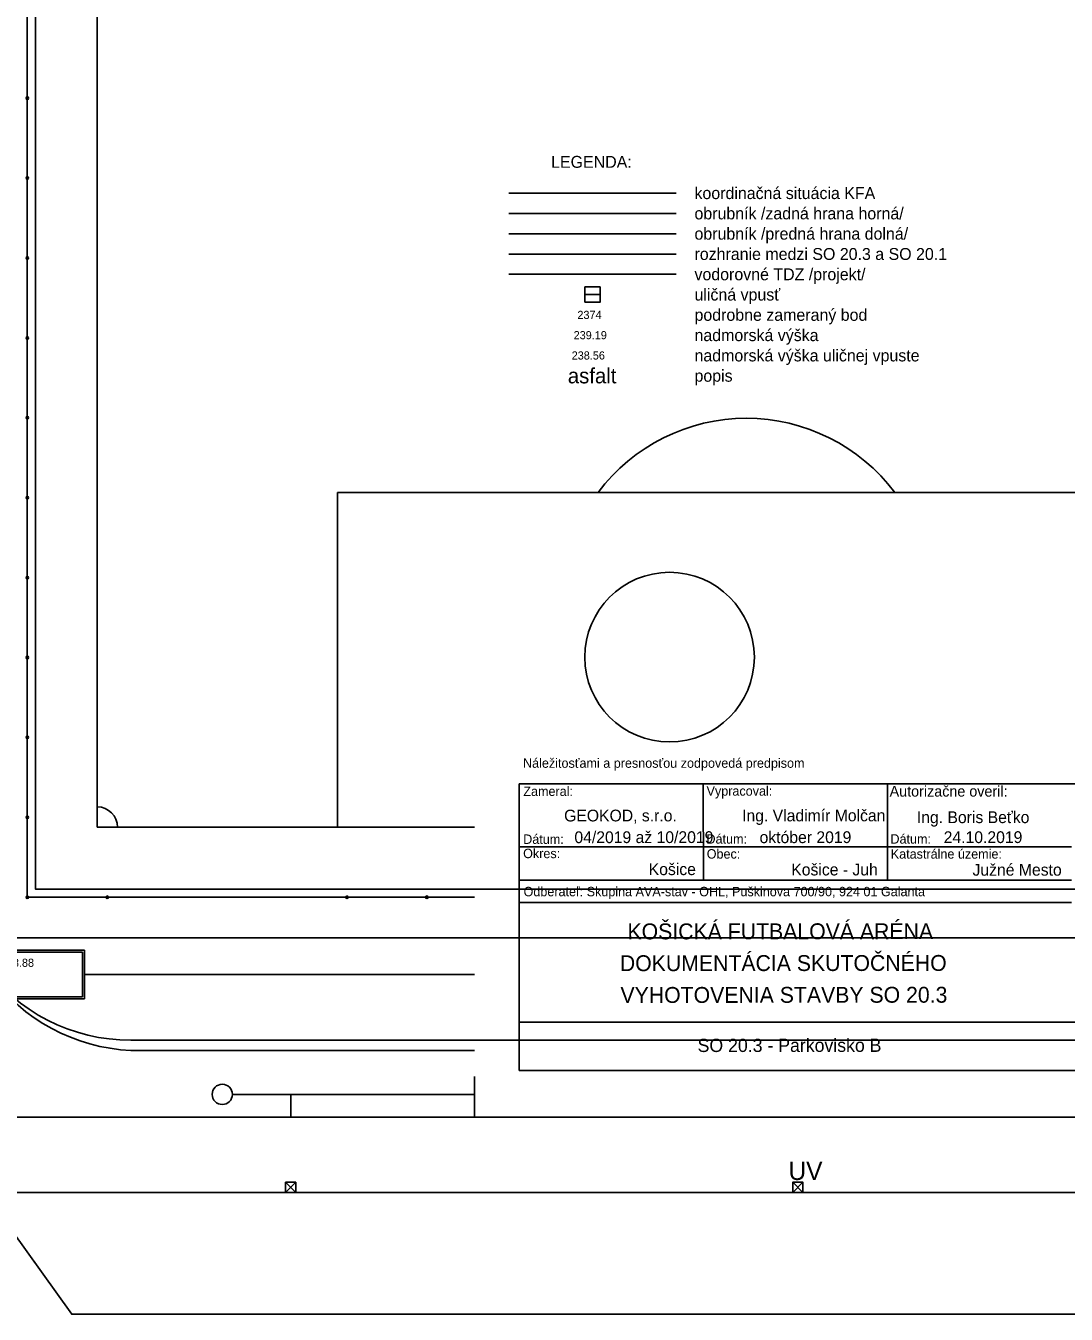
# Model space of a CAD drawing. Extents: x -264222 to -263676, y -1242344 to -1242060.
# Drawn here: x -264118.1 to -264066.8, y -1242315 to -1242251.5 of the extents above; entities that cross this region are included whole.
import ezdxf

# ---------------------------------------------------------------- set-up
doc = ezdxf.new("R2010")
doc.units = 0
for name, color, linetype in [('BODY_VYSKA', 7, 'Continuous'), ('KOORDINACNA_SITUACIA_DSP', 7, 'Continuous'), ('LEGENDA', 7, 'Continuous'), ('PROJEKT_DRS_OBRUBNIKY_KOMUNIKACIE', 7, 'Continuous'), ('PROJEKT_DRS_TDZ_VODOROVNE', 7, 'Continuous'), ('PROJEKT_DRS_UV_STAVBY', 7, 'Continuous'), ('RAM_NA_TLAC_8xA4_1-200', 7, 'Continuous'), ('ROZPISKA', 7, 'Continuous')]:
    doc.layers.add(name, color=color, linetype=linetype)

msp = doc.modelspace()

# ---------------------------------------------------------------- linework, layer by layer
at = {"layer": 'KOORDINACNA_SITUACIA_DSP'}
for p, q in [((-264118.068, -1242187.532), (-264118.068, -1242294.432)), ((-264117.668, -1242294.032), (-264117.668, -1242187.932)), ((-264114.618, -1242190.982), (-264114.618, -1242290.982)), ((-264118.008, -1242255.057), (-264118.128, -1242255.057)), ((-264118.068, -1242255.117), (-264118.068, -1242254.997)), ((-264118.008, -1242258.995), (-264118.128, -1242258.995)), ((-264118.068, -1242259.055), (-264118.068, -1242258.935)), ((-264118.008, -1242262.932), (-264118.128, -1242262.932)), ((-264118.068, -1242262.992), (-264118.068, -1242262.872)), ((-264118.068, -1242266.93), (-264118.068, -1242266.81)), ((-264118.008, -1242266.87), (-264118.128, -1242266.87)), ((-264118.008, -1242270.807), (-264118.128, -1242270.807)), ((-264118.068, -1242270.867), (-264118.068, -1242270.747)), ((-264118.008, -1242274.745), (-264118.128, -1242274.745)), ((-264118.068, -1242274.805), (-264118.068, -1242274.685)), ((-264062.458, -1242274.482), (-264102.778, -1242274.482)), ((-264102.778, -1242274.482), (-264102.778, -1242290.982)), ((-264118.008, -1242278.682), (-264118.128, -1242278.682)), ((-264118.068, -1242278.742), (-264118.068, -1242278.622)), ((-264118.008, -1242282.62), (-264118.128, -1242282.62)), ((-264118.068, -1242282.68), (-264118.068, -1242282.56)), ((-264118.068, -1242286.617), (-264118.068, -1242286.497)), ((-264118.008, -1242286.557), (-264118.128, -1242286.557)), ((-264118.008, -1242290.495), (-264118.128, -1242290.495)), ((-264118.068, -1242290.555), (-264118.068, -1242290.435)), ((-264114.618, -1242290.982), (-264096.03, -1242290.982)), ((-264096.03, -1242294.032), (-264117.668, -1242294.032)), ((-264118.008, -1242294.432), (-264118.128, -1242294.432)), ((-264118.068, -1242294.492), (-264118.068, -1242294.372)), ((-264118.068, -1242294.432), (-264096.03, -1242294.432)), ((-264114.069, -1242294.432), (-264114.189, -1242294.432)), ((-264114.129, -1242294.492), (-264114.129, -1242294.372)), ((-264102.252, -1242294.432), (-264102.372, -1242294.432)), ((-264102.312, -1242294.492), (-264102.312, -1242294.372)), ((-264098.313, -1242294.432), (-264098.433, -1242294.432)), ((-264098.373, -1242294.492), (-264098.373, -1242294.372)), ((-264115.254, -1242297.036), (-264120.154, -1242297.036)), ((-264115.354, -1242297.136), (-264120.054, -1242297.136)), ((-264115.354, -1242299.336), (-264115.354, -1242297.136)), ((-264115.254, -1242299.436), (-264115.254, -1242297.036)), ((-264115.254, -1242298.236), (-264096.03, -1242298.236)), ((-264120.154, -1242299.436), (-264115.254, -1242299.436)), ((-264120.054, -1242299.336), (-264115.354, -1242299.336)), ((-264096.03, -1242301.482), (-264112.961, -1242301.482)), ((-264096.03, -1242304.147), (-264107.955, -1242304.147)), ((-264105.085, -1242305.266), (-264105.085, -1242304.147))]:
    msp.add_line(p, q, dxfattribs=at)
msp.add_lwpolyline([(-264096.03, -1242296.432), (-264120.018, -1242296.432), (-264120.282, -1242296.432)], dxfattribs=at)
for centre, radius in [((-264118.068, -1242255.057), 0.06), ((-264118.068, -1242258.995), 0.06), ((-264118.068, -1242262.932), 0.06), ((-264118.068, -1242266.87), 0.06), ((-264118.068, -1242270.807), 0.06), ((-264118.068, -1242274.745), 0.06), ((-264118.068, -1242278.682), 0.06), ((-264118.068, -1242282.62), 0.06), ((-264118.068, -1242286.557), 0.06), ((-264118.068, -1242290.495), 0.06), ((-264118.068, -1242294.432), 0.06), ((-264114.129, -1242294.432), 0.06), ((-264102.312, -1242294.432), 0.06), ((-264098.373, -1242294.432), 0.06), ((-264108.455, -1242304.147), 0.5)]:
    msp.add_circle(centre, radius, dxfattribs=at)
for centre, radius, start, end in [((-264082.618, -1242279.982), 9.15, 36.94821, 143.05179), ((-264114.618, -1242290.982), 1, 0, 90), ((-264112.961, -1242292.482), 9, 215.72401, 270)]:
    msp.add_arc(centre, radius, start, end, dxfattribs=at)
at = {"layer": 'LEGENDA'}
for p, q in [((-264094.33, -1242259.736), (-264086.079, -1242259.736)), ((-264094.33, -1242260.736), (-264086.079, -1242260.736)), ((-264094.33, -1242261.736), (-264086.079, -1242261.736)), ((-264094.33, -1242262.736), (-264086.079, -1242262.736)), ((-264094.33, -1242263.736), (-264086.079, -1242263.736))]:
    msp.add_line(p, q, dxfattribs=at)
for points in [[(-264090.579, -1242264.361), (-264089.829, -1242264.361), (-264089.829, -1242265.111), (-264090.579, -1242265.111)], [(-264090.579, -1242265.111), (-264090.579, -1242264.361)], [(-264090.579, -1242264.736), (-264089.829, -1242264.736)]]:
    msp.add_lwpolyline(points, dxfattribs=at)
at = {"layer": 'PROJEKT_DRS_OBRUBNIKY_KOMUNIKACIE'}
for p, q in [((-264204.694, -1242191.482), (-264115.871, -1242314.982)), ((-263971.068, -1242301.482), (-264112.961, -1242301.482)), ((-264050.531, -1242308.982), (-264119.571, -1242308.982)), ((-264115.886, -1242314.982), (-264044.531, -1242314.982))]:
    msp.add_line(p, q, dxfattribs=at)
for points in [[(-264117.668, -1242187.932), (-264047.568, -1242187.932), (-264047.568, -1242294.032), (-264117.668, -1242294.032), (-264117.668, -1242187.932)], [(-263965.143, -1242296.432), (-264120.018, -1242296.432), (-264120.282, -1242296.432)]]:
    msp.add_lwpolyline(points, dxfattribs=at)
msp.add_arc((-264112.961, -1242292.482), 9, 215.72401, 270, dxfattribs=at)
at = {"layer": 'PROJEKT_DRS_TDZ_VODOROVNE'}
msp.add_line((-264112.961, -1242301.982), (-264096.03, -1242301.982), dxfattribs=at)
msp.add_arc((-264112.56, -1242292.924), 9.068, 215.87399, 267.4682, dxfattribs=at)
at = {"layer": 'PROJEKT_DRS_UV_STAVBY'}
for points in [[(-264105.335, -1242308.982), (-264105.335, -1242308.482), (-264104.835, -1242308.482), (-264104.835, -1242308.982), (-264105.335, -1242308.982), (-264104.835, -1242308.482), (-264105.335, -1242308.482), (-264104.835, -1242308.982)], [(-264080.335, -1242308.982), (-264080.335, -1242308.482), (-264079.835, -1242308.482), (-264079.835, -1242308.982), (-264080.335, -1242308.982), (-264079.835, -1242308.482), (-264080.335, -1242308.482), (-264079.835, -1242308.982)]]:
    msp.add_lwpolyline(points, dxfattribs=at)
at = {"layer": 'RAM_NA_TLAC_8xA4_1-200'}
msp.add_line((-264096.03, -1242305.266), (-264096.03, -1242303.266), dxfattribs=at)
msp.add_lwpolyline([(-264222.03, -1242186.466), (-264054.03, -1242186.466), (-264054.03, -1242305.266), (-264222.03, -1242305.266)], close=True, dxfattribs=at)
at = {"layer": 'ROZPISKA'}
for p, q in [((-264093.815, -1242288.848), (-264093.816, -1242302.965)), ((-264093.815, -1242288.848), (-264056.508, -1242288.848)), ((-264084.742, -1242288.847), (-264084.739, -1242293.589)), ((-264075.667, -1242288.85), (-264075.665, -1242293.587)), ((-264093.817, -1242291.946), (-264066.591, -1242291.946)), ((-264093.816, -1242293.587), (-264066.592, -1242293.587)), ((-264093.818, -1242294.699), (-264066.588, -1242294.696)), ((-264093.816, -1242300.585), (-264056.507, -1242300.584)), ((-264093.816, -1242302.965), (-264056.508, -1242302.965))]:
    msp.add_line(p, q, dxfattribs=at)
msp.add_circle((-264086.404, -1242282.601), 4.18, dxfattribs=at)

# ---------------------------------------------------------------- texts
at = {"layer": 'BODY_VYSKA'}
msp.add_text('238.88', height=0.4, dxfattribs=at).set_placement((-264119.374, -1242297.862))
at = {"layer": 'LEGENDA'}
for s, height, p in [('LEGENDA:', 0.5878, (-264092.245, -1242258.489)), ('koordinačná situácia KFA', 0.58781, (-264085.177, -1242260.029)), ('obrubník /zadná hrana horná/', 0.58781, (-264085.177, -1242261.029)), ('obrubník /predná hrana dolná/', 0.58781, (-264085.177, -1242262.029)), ('rozhranie medzi SO 20.3 a SO 20.1', 0.58781, (-264085.177, -1242263.029)), ('vodorovné TDZ /projekt/', 0.58781, (-264085.177, -1242264.029)), ('uličná vpusť', 0.58781, (-264085.177, -1242265.029)), ('2374', 0.4, (-264090.949, -1242265.936)), ('podrobne zameraný bod', 0.58781, (-264085.177, -1242266.029)), ('239.19', 0.4, (-264091.134, -1242266.936)), ('nadmorská výška', 0.58781, (-264085.177, -1242267.029)), ('nadmorská výška uličnej vpuste', 0.58781, (-264085.177, -1242268.029)), ('238.56', 0.4, (-264091.23, -1242267.936)), ('asfalt', 0.75, (-264091.422, -1242269.111)), ('popis', 0.5878, (-264085.177, -1242269.029))]:
    msp.add_text(s, height=height, dxfattribs=at).set_placement(p)
at = {"layer": 'PROJEKT_DRS_UV_STAVBY'}
msp.add_text('UV', height=0.9, rotation=359.8587, dxfattribs=at).set_placement((-264080.543, -1242308.366))
at = {"layer": 'ROZPISKA'}
for s, height, rotation, p in [('Náležitosťami a presnosťou zodpovedá predpisom', 0.46373, 0.00155, (-264093.629, -1242288.054)), ('Zameral:', 0.4637, 0.00155, (-264093.615, -1242289.442)), ('Vypracoval:', 0.46373, 0.00155, (-264084.582, -1242289.429)), ('Autorizačne overil:', 0.52854, 0.00155, (-264075.557, -1242289.474)), ('GEOKOD, s.r.o.', 0.57952, 0.04559, (-264091.603, -1242290.699)), ('Ing. Vladimír Molčan', 0.57964, 0.04559, (-264082.83, -1242290.697)), ('Ing. Boris Beťko', 0.57992, 0.04559, (-264074.215, -1242290.783)), ('Dátum:', 0.4637, 0.00155, (-264093.621, -1242291.804)), ('04/2019 až 10/2019', 0.57952, 0.04559, (-264091.097, -1242291.767)), ('Dátum:', 0.4637, 0.00155, (-264084.587, -1242291.791)), ('október 2019', 0.57952, 0.04559, (-264081.967, -1242291.767)), ('Dátum:', 0.4637, 0.00155, (-264075.517, -1242291.792)), ('24.10.2019', 0.5795, 0.04559, (-264072.891, -1242291.765)), ('Okres:', 0.4637, 0.00155, (-264093.624, -1242292.507)), ('Obec:', 0.4637, 0.00155, (-264084.574, -1242292.529)), ('Katastrálne územie:', 0.46373, 0.00155, (-264075.5, -1242292.531)), ('Košice', 0.5798, 0.04559, (-264087.433, -1242293.344)), ('Košice - Juh', 0.57992, 0.04559, (-264080.406, -1242293.361)), ('Južné Mesto', 0.57992, 0.04559, (-264071.47, -1242293.372)), ('Odberateľ: Skupina AVA-stav - OHL, Puškinova 700/90, 924 01 Galanta', 0.46361, 0.00155, (-264093.603, -1242294.386)), ('KOŠICKÁ FUTBALOVÁ ARÉNA', 0.78289, 0.04559, (-264088.482, -1242296.51)), ('DOKUMENTÁCIA SKUTOČNÉHO', 0.78289, 0.04559, (-264088.856, -1242298.076)), ('VYHOTOVENIA STAVBY SO 20.3', 0.78289, 0.04559, (-264088.825, -1242299.642)), ('SO 20.3 - Parkovisko B', 0.65225, 0.04559, (-264085.023, -1242302.061))]:
    msp.add_text(s, height=height, rotation=rotation, dxfattribs=at).set_placement(p)

doc.saveas('drawing.dxf')
